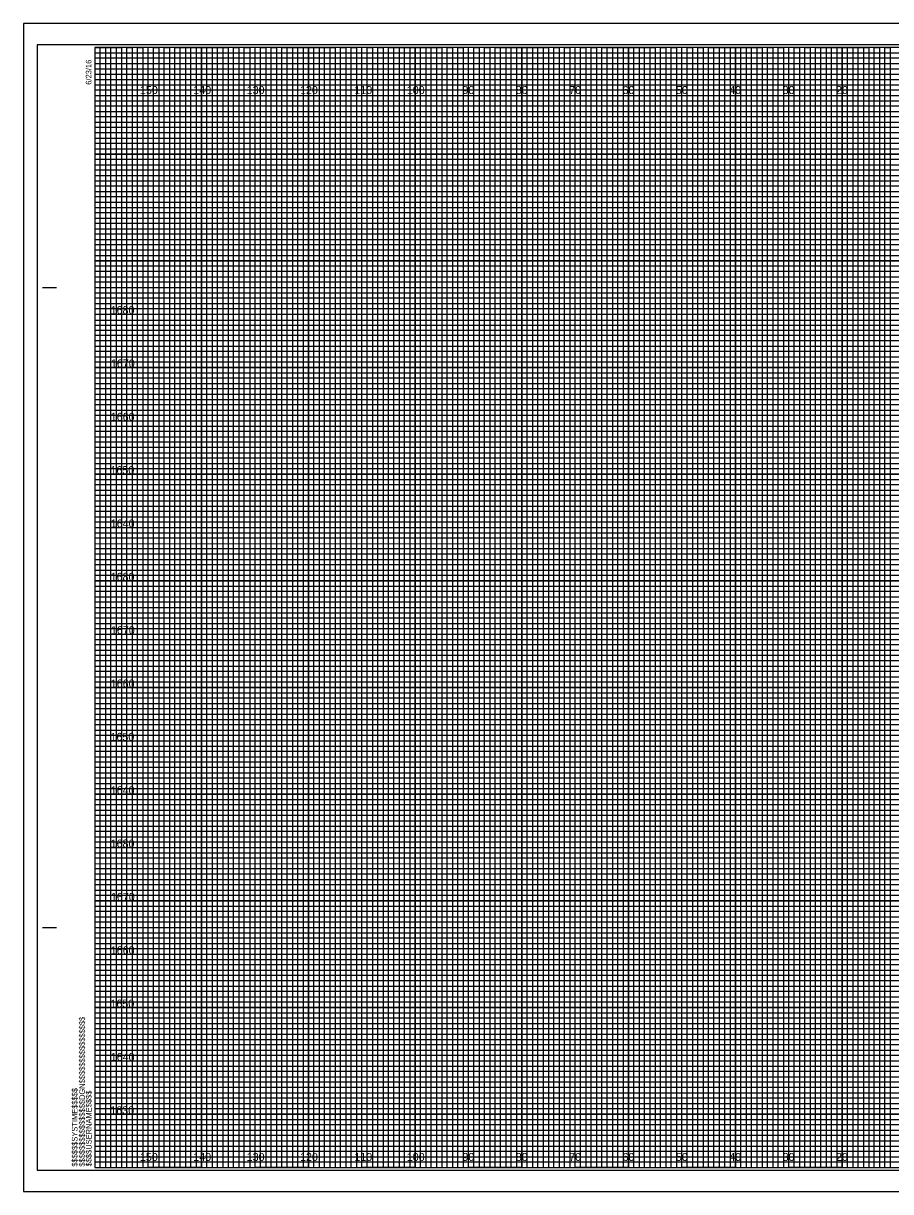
# Model space of a CAD drawing. Extents: x -13 to 323, y -5 to 2414.
# Drawn here: x -13.4 to 149.1, y 1315.5 to 1534.5 of the extents above; entities that cross this region are included whole.
import ezdxf

# ---------------------------------------------------------------- set-up
doc = ezdxf.new("R2010")
doc.units = 0
for name, color, linetype in [('Prop XS Elevation Labels', 7, 'Continuous'), ('Prop XS Offset Labels', 7, 'Continuous'), ('Sheet Cross Section CELL', 7, 'Continuous'), ('Sheet Cross Section Grid Major CELL', 7, 'Continuous'), ('Sheet Cross Section Grid Middle CELL', 7, 'Continuous'), ('Sheet Cross Section Grid Minor 1 CELL', 7, 'Continuous'), ('Sheet Cross Section Grid Minor 2 CELL', 7, 'Continuous'), ('Sheet Cutting Line CELL', 7, 'Continuous'), ('Sheet DOT Grid CELL', 7, 'Continuous'), ('Sheet Plot Border Inside CELL', 7, 'Continuous'), ('Sheet Plot Border Outside CELL', 7, 'Continuous')]:
    doc.layers.add(name, color=color, linetype=linetype)

msp = doc.modelspace()

# ---------------------------------------------------------------- linework, layer by layer
at = {"layer": 'Sheet Cross Section CELL'}
for p, q in [((-9.8, 1485), (-7.3, 1485)), ((-9.7, 1485), (-7.2, 1485)), ((-9.8, 1365), (-7.3, 1365)), ((-9.7, 1365), (-7.2, 1365)), ((0, 1320), (0, 1320)), ((0, 1320), (0, 1320)), ((0, 1320), (0, 1320)), ((0, 1320), (0, 1320)), ((0, 1320), (0, 1320)), ((0, 1320), (0, 1320)), ((0, 1320), (0, 1320))]:
    msp.add_line(p, q, dxfattribs=at)
msp.add_lwpolyline([(320, 1530), (0, 1530), (0, 1320), (320, 1320)], close=True, dxfattribs=at)
at = {"layer": 'Sheet Cross Section Grid Major CELL'}
for p, q in [((10, 1530), (0, 1530)), ((10, 1320), (10, 1530)), ((30, 1530), (20, 1530)), ((20, 1530), (20, 1320)), ((30, 1320), (30, 1530)), ((50, 1530), (40, 1530)), ((40, 1530), (40, 1320)), ((50, 1320), (50, 1530)), ((70, 1530), (60, 1530)), ((60, 1530), (60, 1320)), ((70, 1320), (70, 1530)), ((90, 1530), (80, 1530)), ((80, 1530), (80, 1320)), ((90, 1320), (90, 1530)), ((110, 1530), (100, 1530)), ((100, 1530), (100, 1320)), ((110, 1320), (110, 1530)), ((130, 1530), (120, 1530)), ((120, 1530), (120, 1320)), ((130, 1320), (130, 1530)), ((150, 1530), (140, 1530)), ((140, 1530), (140, 1320)), ((20, 1320), (10, 1320)), ((40, 1320), (30, 1320)), ((60, 1320), (50, 1320)), ((80, 1320), (70, 1320)), ((100, 1320), (90, 1320)), ((120, 1320), (110, 1320)), ((140, 1320), (130, 1320))]:
    msp.add_line(p, q, dxfattribs=at)
for points in [[(0, 1520), (320, 1520), (320, 1510), (0, 1510)], [(0, 1500), (320, 1500), (320, 1490), (0, 1490)], [(0, 1480), (320, 1480), (320, 1470), (0, 1470)], [(0, 1460), (320, 1460), (320, 1450), (0, 1450)], [(0, 1440), (320, 1440), (320, 1430), (0, 1430)], [(0, 1420), (320, 1420), (320, 1410), (0, 1410)], [(0, 1400), (320, 1400), (320, 1390), (0, 1390)], [(0, 1380), (320, 1380), (320, 1370), (0, 1370)], [(0, 1360), (320, 1360), (320, 1350), (0, 1350)], [(0, 1340), (320, 1340), (320, 1330), (0, 1330)]]:
    msp.add_lwpolyline(points, dxfattribs=at)
at = {"layer": 'Sheet Cross Section Grid Middle CELL'}
for points in [[(0, 1530), (5, 1530), (5, 1320), (15, 1320), (15, 1530), (25, 1530), (25, 1320), (35, 1320), (35, 1530), (45, 1530), (45, 1320), (55, 1320), (55, 1530), (65, 1530), (65, 1320), (75, 1320), (75, 1530), (85, 1530), (85, 1320), (95, 1320), (95, 1530), (105, 1530), (105, 1320), (115, 1320), (115, 1530), (125, 1530), (125, 1320), (135, 1320), (135, 1530), (145, 1530), (145, 1320), (155, 1320)], [(0, 1525), (275, 1525)], [(0, 1505), (320, 1505), (320, 1515), (0, 1515)], [(0, 1485), (320, 1485), (320, 1495), (0, 1495)], [(0, 1465), (320, 1465), (320, 1475), (0, 1475)], [(0, 1445), (320, 1445), (320, 1455), (0, 1455)], [(0, 1425), (320, 1425), (320, 1435), (0, 1435)], [(0, 1405), (320, 1405), (320, 1415), (0, 1415)], [(0, 1385), (320, 1385), (320, 1395), (0, 1395)], [(0, 1365), (320, 1365), (320, 1375), (0, 1375)], [(0, 1345), (320, 1345), (320, 1355), (0, 1355)], [(0, 1325), (320, 1325), (320, 1335), (0, 1335)]]:
    msp.add_lwpolyline(points, dxfattribs=at)
at = {"layer": 'Sheet Cross Section Grid Minor 1 CELL'}
for p, q in [((0, 1529), (260, 1529)), ((260, 1527.98), (0, 1527.98)), ((0, 1527.98), (0, 1527)), ((0, 1527), (260, 1527)), ((260, 1525.89), (0, 1525.89)), ((0, 1525.89), (0, 1524)), ((0, 1524), (320, 1524))]:
    msp.add_line(p, q, dxfattribs=at)
for points in [[(0, 1523), (270, 1523), (320, 1523), (320, 1522), (0, 1522)], [(0, 1521), (320, 1521), (320, 1519), (0, 1519)], [(0, 1518), (320, 1518), (320, 1517), (0, 1516.98)], [(0, 1516), (320, 1516), (320, 1514), (0, 1514)], [(0, 1513), (320, 1513), (320, 1512), (0, 1512)], [(0, 1511), (320, 1511), (320, 1509), (0, 1509)], [(0, 1508), (320, 1508), (320, 1507), (0, 1507)], [(0, 1506), (320, 1506), (320, 1504), (0, 1504)], [(0, 1503), (320, 1503), (320, 1502), (0, 1502)], [(0, 1501), (320, 1501), (320, 1499), (0, 1499)], [(0, 1498), (320, 1498), (320, 1497), (0, 1497)], [(0, 1496), (320, 1496), (320, 1493.95), (320, 1493), (320, 1492), (0, 1492)], [(0, 1494), (320, 1494), (320, 1493), (0, 1493)], [(0, 1491), (320, 1491), (320, 1489), (0, 1489.03)], [(0, 1489.03), (320, 1489), (320, 1488), (0, 1488)], [(0, 1487), (320, 1487), (320, 1486), (0, 1486)], [(0, 1484), (320, 1484), (320, 1483), (0, 1483)], [(0, 1482), (320, 1482), (320, 1481), (0, 1481)], [(-0.07, 1478.89), (320, 1478.89), (320, 1477.88), (-0.07, 1477.88)], [(0, 1477), (320, 1477), (320, 1476), (0, 1476)], [(0, 1474), (320, 1474), (320, 1473), (0, 1473)], [(0, 1472), (320, 1472), (320, 1471), (0, 1471)], [(0, 1469), (320, 1469), (320, 1468), (0, 1468)], [(0, 1467), (320, 1467), (320, 1466), (0, 1466)], [(0, 1464), (320, 1464), (320, 1463), (0, 1463)], [(0, 1462), (320, 1462), (320, 1461), (0, 1461)], [(0, 1459), (320, 1459), (319.99, 1457.98), (0, 1458)], [(0, 1457), (320, 1457), (320, 1456), (0, 1456)], [(0, 1454), (320, 1454), (320, 1453), (0, 1453)], [(0, 1452), (320, 1452), (320, 1451), (0, 1451)], [(0, 1449), (320, 1449), (320, 1448), (0, 1448)], [(0, 1447), (320, 1447), (320, 1446), (0, 1446)], [(0, 1444), (320, 1444), (320, 1443), (0, 1443)], [(0, 1442), (320, 1442), (320, 1441), (0, 1441)], [(0, 1439), (320, 1439), (320, 1438), (0, 1438)], [(0, 1436.99), (320.07, 1436.91), (320, 1436), (0, 1436)], [(0, 1434), (320, 1434), (320, 1433), (0, 1433)], [(0, 1432), (320, 1432), (320, 1431), (0, 1431)], [(0, 1429), (320, 1429), (320, 1428), (0, 1428)], [(0, 1427), (320, 1427), (320, 1426), (0, 1426)], [(0, 1424), (320, 1424), (320, 1423), (0, 1423)], [(0, 1422), (320, 1422), (320, 1421), (0, 1421)], [(0, 1419), (320, 1419), (320, 1418), (0, 1418)], [(0, 1417), (320, 1417), (320, 1416), (0, 1416)], [(0, 1414), (320, 1414), (320, 1413), (0, 1413)], [(0, 1412), (320, 1412), (320, 1411), (0, 1411)], [(0, 1409), (320, 1409), (320, 1408), (0, 1408)], [(0, 1407), (320, 1407), (320, 1406), (0, 1406)], [(0, 1404), (320, 1404), (320, 1403), (0, 1403)], [(0, 1402), (320, 1402), (320, 1401), (0, 1401)], [(0, 1399), (320, 1399), (319.99, 1397.98), (0, 1398)], [(0, 1397), (320, 1397), (320, 1396), (0, 1396)], [(0, 1394), (320, 1394), (320, 1393), (0, 1393)], [(0, 1392), (320, 1392), (320, 1391), (0, 1391)], [(0, 1389), (320, 1389), (320, 1388), (0, 1388)], [(0, 1387), (320, 1387), (320, 1386), (0, 1386)], [(0, 1384), (320, 1384), (320, 1383), (0, 1383)], [(0, 1382), (320, 1382), (320, 1381), (0, 1381)], [(0, 1379), (320, 1379), (320, 1378), (0, 1378)], [(0, 1376.99), (320.07, 1376.91), (320, 1376), (0, 1376)], [(0, 1374), (320, 1374), (320, 1373), (0, 1373)], [(0, 1372), (320, 1372), (320, 1371), (0, 1371)], [(0, 1369), (320, 1369), (320, 1368), (0, 1368)], [(0, 1367), (320, 1367), (320, 1366), (0, 1366)], [(0, 1364), (320, 1364), (320, 1363), (0, 1363)], [(0, 1362), (320, 1362), (320, 1361), (0, 1361)], [(0, 1359), (320, 1359), (320, 1358), (0, 1358)], [(0, 1357), (320, 1357), (320, 1356), (0, 1356)], [(0, 1354), (320, 1354), (320, 1353), (0, 1353)], [(0, 1352), (320, 1352), (320, 1351), (0, 1351)], [(0, 1349), (320, 1349), (320, 1348), (0, 1348)], [(0, 1347), (320, 1347), (320, 1346), (0, 1346)], [(0, 1344), (320, 1344), (320, 1343), (0, 1343)], [(0, 1342), (320, 1342), (320, 1341), (0, 1341)], [(0, 1339), (320, 1339), (320, 1338), (0, 1338)], [(0, 1337), (320, 1337), (320, 1336), (0, 1336)], [(0, 1334), (320, 1334), (320, 1333), (0, 1333)], [(0, 1332), (320, 1332), (320, 1331), (0, 1331)], [(0, 1329), (320, 1329), (320, 1328), (0, 1328)], [(0, 1327), (320, 1327), (320, 1326), (0, 1326)], [(0, 1324), (320, 1324), (320, 1323), (0, 1323)], [(0, 1322), (320, 1322), (320, 1321), (0, 1321)]]:
    msp.add_lwpolyline(points, dxfattribs=at)
at = {"layer": 'Sheet Cross Section Grid Minor 2 CELL'}
for points in [[(0, 1320), (1, 1320), (1, 1530), (2, 1530), (2, 1320)], [(2, 1320), (3, 1320), (3, 1530), (4, 1530), (4, 1320)], [(5, 1320), (6, 1320), (6, 1530), (7, 1530), (7, 1320)], [(7, 1320), (8, 1320), (8, 1530), (9, 1530), (9, 1320)], [(10, 1320), (11, 1320), (11, 1530), (12, 1530), (12, 1320)], [(12, 1320), (13, 1320), (13, 1530), (14, 1530), (14, 1320)], [(15, 1320), (16, 1320), (16, 1530), (17, 1530), (17, 1320)], [(17, 1320), (18, 1320), (18, 1530), (19, 1530), (19, 1320)], [(20, 1320), (21, 1320), (21, 1530), (22, 1530), (22, 1320)], [(22, 1320), (23, 1320), (23, 1530), (24, 1530), (24, 1320)], [(25, 1320), (26, 1320), (26, 1530), (27, 1530), (27, 1320)], [(27, 1320), (28, 1320), (28, 1530), (29, 1530), (29, 1320)], [(30, 1320), (31, 1320), (31, 1530), (32, 1530), (32, 1320)], [(32, 1320), (33, 1320), (33, 1530), (34, 1530), (34, 1320)], [(35, 1320), (36, 1320), (36, 1530), (37, 1530), (37, 1320)], [(37, 1320), (38, 1320), (38, 1530), (39, 1530), (39, 1320)], [(40, 1320), (41, 1320), (41, 1530), (42, 1530), (42, 1320)], [(42, 1320), (43, 1320), (43, 1530), (44, 1530), (44, 1320)], [(45, 1320), (46, 1320), (46, 1530), (47, 1530), (47, 1320)], [(47, 1320), (48, 1320), (48, 1530), (49, 1530), (49, 1320)], [(50, 1320), (51, 1320), (51, 1530), (52, 1530), (52, 1320)], [(52, 1320), (53, 1320), (53, 1530), (54, 1530), (54, 1320)], [(55, 1320), (56, 1320), (56, 1530), (57, 1530), (57, 1320)], [(57, 1320), (58, 1320), (58, 1530), (59, 1530), (59, 1320)], [(60, 1320), (61, 1320), (61, 1530), (62, 1530), (62, 1320)], [(62, 1320), (63, 1320), (63, 1530), (64, 1530), (64, 1320)], [(65, 1320), (66, 1320), (66, 1530), (67, 1530), (67, 1320)], [(67, 1320), (68, 1320), (68, 1530), (69, 1530), (69, 1320)], [(70, 1320), (71, 1320), (71, 1530), (72, 1530), (72, 1320)], [(72, 1320), (73, 1320), (73, 1530), (74, 1530), (74, 1320)], [(75, 1320), (76, 1320), (76, 1530), (77, 1530), (77, 1320)], [(77, 1320), (78, 1320), (78, 1530), (79, 1530), (79, 1320)], [(80, 1320), (81, 1320), (81, 1530), (82, 1530), (82, 1320)], [(82, 1320), (83, 1320), (83, 1530), (84, 1530), (84, 1320)], [(85, 1320), (86, 1320), (86, 1530), (87, 1530), (87, 1320)], [(87, 1320), (88, 1320), (88, 1530), (89, 1530), (89, 1320)], [(90, 1320), (91, 1320), (91, 1530), (92, 1530), (92, 1320)], [(92, 1320), (93, 1320), (93, 1530), (94, 1530), (94, 1320)], [(95, 1320), (96, 1320), (96, 1530), (97, 1530), (97, 1320)], [(97, 1320), (98, 1320), (98, 1530), (99, 1530), (99, 1320)], [(100, 1320), (101, 1320), (101, 1530), (102, 1530), (102, 1320)], [(102, 1320), (103, 1320), (103, 1530), (104, 1530), (104, 1320)], [(105, 1320), (106, 1320), (106, 1530), (107, 1530), (107, 1320)], [(107, 1320), (108, 1320), (108, 1530), (109, 1530), (109, 1320)], [(110, 1320), (111, 1320), (111, 1530), (112, 1530), (112, 1320)], [(112, 1320), (113, 1320), (113, 1530), (114, 1530), (114, 1320)], [(115, 1320), (116, 1320), (116, 1530), (117, 1530), (117, 1320)], [(117, 1320), (118, 1320), (118, 1530), (119, 1530), (119, 1320)], [(120, 1320), (121, 1320), (121, 1530), (122, 1530), (122, 1320)], [(122, 1320), (123, 1320), (123, 1530), (124, 1530), (124, 1320)], [(125, 1320), (126, 1320), (126, 1530), (127, 1530), (127, 1320)], [(127, 1320), (128, 1320), (128, 1530), (129, 1530), (129, 1320)], [(130, 1320), (131, 1320), (131, 1530), (132, 1530), (132, 1320)], [(132, 1320), (133, 1320), (133, 1530), (134, 1530), (134, 1320)], [(135, 1320), (136, 1320), (136, 1530), (137, 1530), (137, 1320)], [(137, 1320), (138, 1320), (138, 1530), (139, 1530), (139, 1320)], [(140, 1320), (141, 1320), (141, 1530), (142, 1530), (142, 1320)], [(142, 1320), (143, 1320), (143, 1530), (144, 1530), (144, 1320)], [(145, 1320), (146, 1320), (146, 1530), (147, 1530), (147, 1320)], [(147, 1320), (148, 1320), (148, 1530), (149, 1530), (149, 1320)]]:
    msp.add_lwpolyline(points, dxfattribs=at)
at = {"layer": 'Sheet Cutting Line CELL'}
for p, q in [((323.3, 1534.5), (-13.4, 1534.5)), ((-13.4, 1534.5), (-13.4, 1315.5)), ((-13.4, 1315.5), (323.3, 1315.5))]:
    msp.add_line(p, q, dxfattribs=at)
at = {"layer": 'Sheet DOT Grid CELL'}
for p, q in [((10, 1320), (10, 1530)), ((20, 1320), (20, 1530)), ((30, 1320), (30, 1530)), ((40, 1320), (40, 1530)), ((50, 1320), (50, 1530)), ((60, 1320), (60, 1530)), ((70, 1320), (70, 1530)), ((80, 1320), (80, 1530)), ((90, 1320), (90, 1530)), ((100, 1320), (100, 1530)), ((110, 1320), (110, 1530)), ((120, 1320), (120, 1530)), ((130, 1320), (130, 1530)), ((140, 1320), (140, 1530)), ((0, 1520), (320, 1520)), ((0, 1510), (320, 1510)), ((0, 1500), (320, 1500)), ((0, 1490), (320, 1490)), ((0, 1480), (320, 1480)), ((0, 1470), (320, 1470)), ((0, 1460), (320, 1460)), ((0, 1450), (320, 1450)), ((0, 1440), (320, 1440)), ((0, 1430), (320, 1430)), ((0, 1420), (320, 1420)), ((0, 1410), (320, 1410)), ((0, 1400), (320, 1400)), ((0, 1390), (320, 1390)), ((0, 1380), (320, 1380)), ((0, 1370), (320, 1370)), ((0, 1360), (320, 1360)), ((0, 1350), (320, 1350)), ((0, 1340), (320, 1340)), ((0, 1330), (320, 1330))]:
    msp.add_line(p, q, dxfattribs=at)
at = {"layer": 'Sheet Plot Border Inside CELL'}
msp.add_lwpolyline([(-10.8, 1319.5), (322.4, 1319.5), (322.4, 1530.5), (-10.8, 1530.5)], close=True, dxfattribs=at)
at = {"layer": 'Sheet Plot Border Outside CELL'}
msp.add_lwpolyline([(-13.4, 1315.5), (323.3, 1315.5), (323.3, 1534.5), (-13.4, 1534.5)], close=True, dxfattribs=at)

# ---------------------------------------------------------------- texts
at = {"layer": 'Prop XS Elevation Labels'}
for s, p in [('1680', (2.95, 1480)), ('1670', (3, 1470)), ('1660', (2.97, 1460)), ('1650', (2.92, 1450)), ('1640', (2.97, 1440)), ('1680', (2.95, 1430)), ('1670', (3, 1420)), ('1660', (2.97, 1410)), ('1650', (2.92, 1400)), ('1640', (2.97, 1390)), ('1680', (2.95, 1380)), ('1670', (3, 1370)), ('1660', (2.97, 1360)), ('1650', (2.92, 1350)), ('1640', (2.97, 1340)), ('1630', (2.89, 1330))]:
    msp.add_text(s, height=1.5, dxfattribs=at).set_placement(p)
at = {"layer": 'Prop XS Offset Labels'}
for s, p in [('150', (8.44, 1521.25)), ('140', (18.44, 1521.25)), ('130', (28.44, 1521.25)), ('120', (38.44, 1521.25)), ('110', (48.62, 1521.25)), ('100', (58.44, 1521.25)), ('90', (68.86, 1521.25)), ('80', (78.86, 1521.25)), ('70', (88.86, 1521.25)), ('60', (98.86, 1521.25)), ('50', (108.86, 1521.25)), ('40', (118.86, 1521.25)), ('30', (128.86, 1521.25)), ('20', (138.86, 1521.25)), ('150', (8.44, 1321.25)), ('140', (18.44, 1321.25)), ('130', (28.44, 1321.25)), ('120', (38.44, 1321.25)), ('110', (48.62, 1321.25)), ('100', (58.44, 1321.25)), ('90', (68.86, 1321.25)), ('80', (78.86, 1321.25)), ('70', (88.86, 1321.25)), ('60', (98.86, 1321.25)), ('50', (108.86, 1321.25)), ('40', (118.86, 1321.25)), ('30', (128.86, 1321.25)), ('20', (138.86, 1321.25))]:
    msp.add_text(s, height=1.5, dxfattribs=at).set_placement(p)
at = {"layer": 'Sheet Cross Section CELL'}
for s, p in [('6/23/16', (-0.65, 1523)), ('$$$$$$$$$$$$$$$$DGN$$$$$$$$$$$$$$$$', (-1.88, 1320.18)), ('$$$$$$SYSTIME$$$$$', (-3.26, 1320.18)), ('$$$$USERNAME$$$$', (-0.62, 1320.23))]:
    msp.add_text(s, height=1.05, rotation=90, dxfattribs=at).set_placement(p)

doc.saveas('drawing.dxf')
